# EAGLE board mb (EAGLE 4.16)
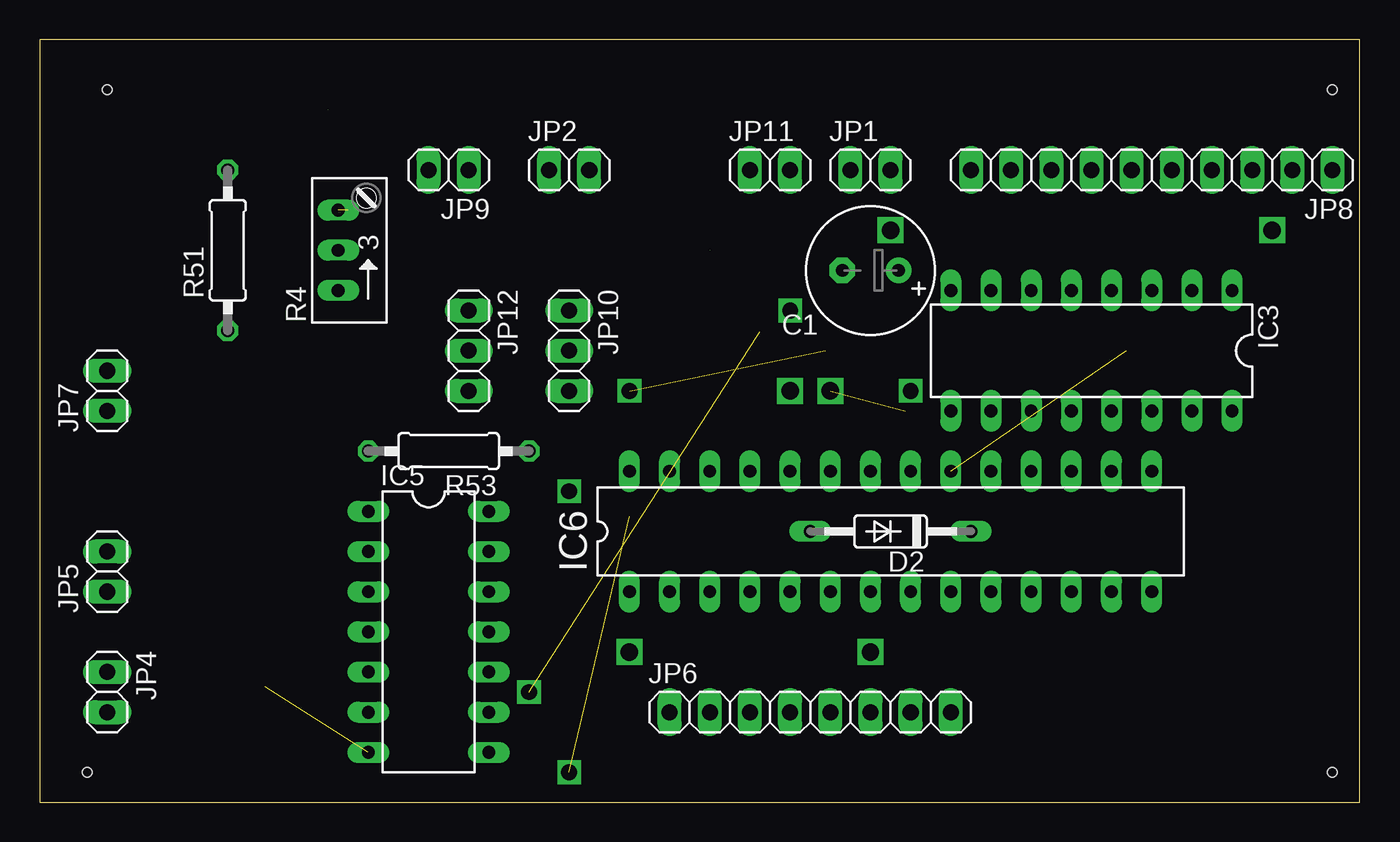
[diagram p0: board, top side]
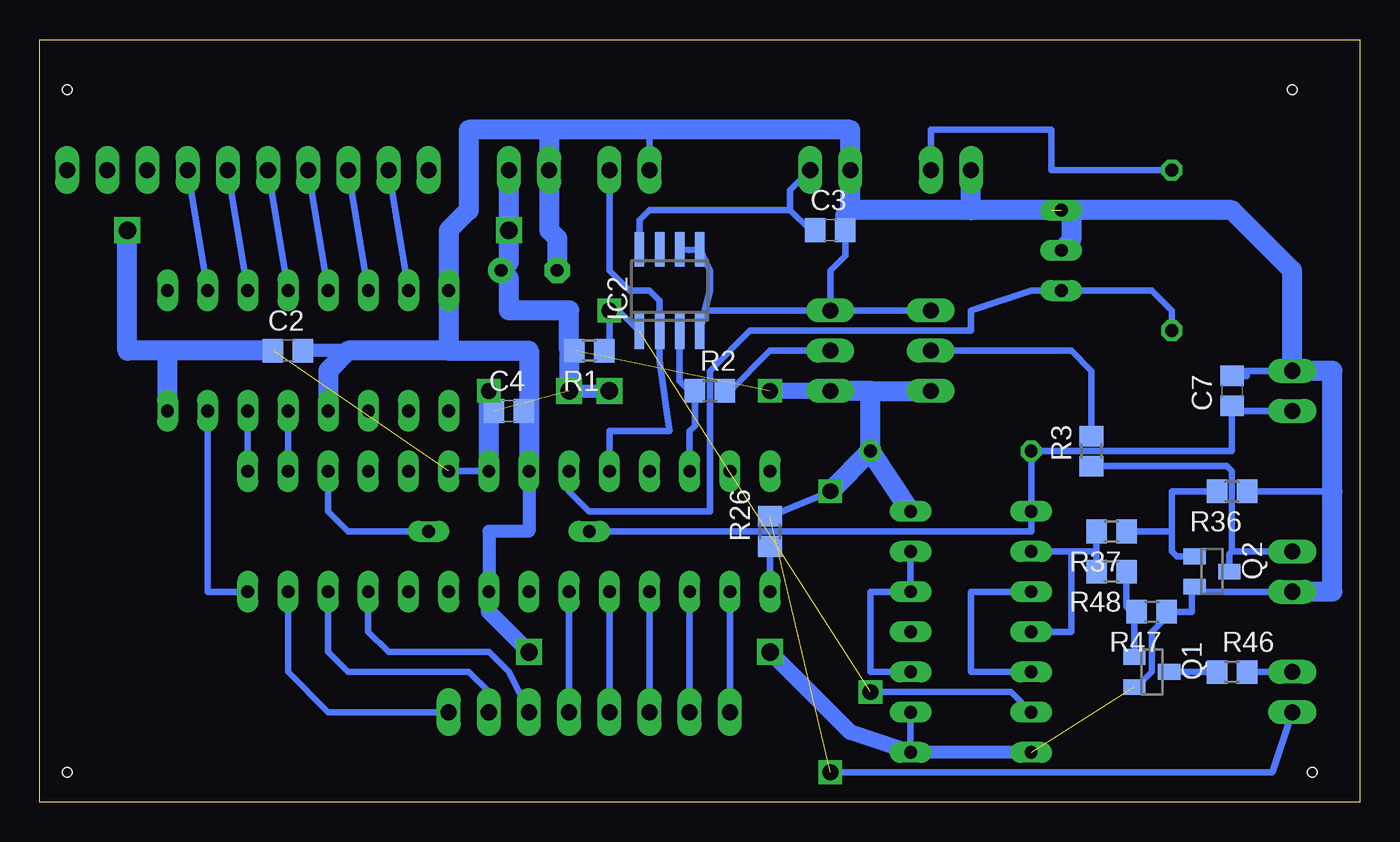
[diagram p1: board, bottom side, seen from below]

Size 83.49 x 48.25 mm. Coordinates in mm from the lower left corner, seen from the top.
Outline: 0,0 83.49,0 83.49,48.25 0,48.25 0,0
Copper layers (1*16): Top 0.035mm / dielectric 1.5mm / Bottom 0.035mm
Design rules "default": minimum track width 10mil, minimum drill 24mil, track to track 8mil, track to pad 8mil, pad to pad 8mil, via to via 8mil, smd to smd 8mil, copper to edge 40mil, drill to drill 8mil, minimum pad ring 10mil, minimum via ring 8mil, stop-mask expansion 4mil, vias tented up to drill 0mil, thermal gap 10mil
Holes 0.6 mm at 4.28,45.08 81.75,45.08 81.75,1.9 3.01,1.9

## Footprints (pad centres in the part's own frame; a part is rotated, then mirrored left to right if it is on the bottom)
E3,5-8 = drill 0.813 pad 1.6 round: + -1.778,0 | drill 0.813 pad 1.6 octagon: - 1.778,0
C0805 = smd 1.3 x 1.5: 1 -0.95,0; 2 0.95,0
DO35-10 = drill 0.813 long: A 5.08,0; C -5.08,0
SO08 = smd 0.6 x 2.2: 1 -1.905,-2.6; 2 -0.635,-2.6; 3 0.635,-2.6; 4 1.905,-2.6; 5 1.905,2.6; 6 0.635,2.6; 7 -0.635,2.6; 8 -1.905,2.6
DIL16 = drill 0.813 long: 1 -8.89,-3.81; 2 -6.35,-3.81; 3 -3.81,-3.81; 4 -1.27,-3.81; 5 1.27,-3.81; 6 3.81,-3.81; 7 6.35,-3.81; 8 8.89,-3.81; 9 8.89,3.81; 10 6.35,3.81; 11 3.81,3.81; 12 1.27,3.81; 13 -1.27,3.81; 14 -3.81,3.81; 15 -6.35,3.81; 16 -8.89,3.81
DIL14 = drill 0.813 long: 1 -7.62,-3.81; 2 -5.08,-3.81; 3 -2.54,-3.81; 4 0,-3.81; 5 2.54,-3.81; 6 5.08,-3.81; 7 7.62,-3.81; 8 7.62,3.81; 9 5.08,3.81; 10 2.54,3.81; 11 0,3.81; 12 -2.54,3.81; 13 -5.08,3.81; 14 -7.62,3.81
DIL28-3 = drill 0.813 long: 1 -16.51,-3.81; 2 -13.97,-3.81; 3 -11.43,-3.81; 4 -8.89,-3.81; 5 -6.35,-3.81; 6 -3.81,-3.81; 7 -1.27,-3.81; 8 1.27,-3.81; 9 3.81,-3.81; 10 6.35,-3.81; 11 8.89,-3.81; 12 11.43,-3.81; 13 13.97,-3.81; 14 16.51,-3.81; 15 16.51,3.81; 16 13.97,3.81; 17 11.43,3.81; 18 8.89,3.81; 19 6.35,3.81; 20 3.81,3.81; 21 1.27,3.81; 22 -1.27,3.81; 23 -3.81,3.81; 24 -6.35,3.81; 25 -8.89,3.81; 26 -11.43,3.81; 27 -13.97,3.81; 28 -16.51,3.81
1X02 = drill 1.016 long: 1 -1.27,0; 2 1.27,0
1X08 = drill 1.016 long: 1 -8.89,0; 2 -6.35,0; 3 -3.81,0; 4 -1.27,0; 5 1.27,0; 6 3.81,0; 7 6.35,0; 8 8.89,0
1X10 = drill 1.016 long: 1 -11.43,0; 2 -8.89,0; 3 -6.35,0; 4 -3.81,0; 5 -1.27,0; 6 1.27,0; 7 3.81,0; 8 6.35,0; 9 8.89,0; 10 11.43,0
1X03 = drill 1.016 long: 1 -2.54,0; 2 0,0; 3 2.54,0
SOT23 = smd 1 x 1.4: 1 -0.95,-1.1; 2 0.95,-1.1; 3 0,1.1
R0805 = smd 1.3 x 1.5: 1 -0.95,0; 2 0.95,0
RJ9W = drill 0.813 long: A 2.54,0.635; E -2.54,0.635; S 0,0.635
0207/10 = drill 0.813 octagon: 1 -5.08,0; 2 5.08,0

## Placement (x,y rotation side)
C1  10uF 10V  [E3,5-8]  52.54,33.65 180 top
C2  0.1uF  [C0805]  67.78,28.57 0 bottom
C3  [C0805]  33.49,36.19 0 bottom
C4  0.1uF  [C0805]  53.81,24.76 0 bottom
C7  [C0805]  8.09,26.03 90 bottom
D2  BA243A  [DO35-10]  53.81,17.14 180 top
IC2  LM393AN  [SO08]  43.65,32.38 0 bottom
IC3  74LS145N  [DIL16]  66.51,28.57 180 top
IC5  4011N  [DIL14]  24.6,10.79 270 top
IC6  MEGA8-P  [DIL28-3]  53.81,17.14 0 top
JP1  [1X02]  52.54,40 0 top
JP2  [1X02]  33.49,40 0 top
JP4  [1X02]  4.28,6.98 270 top
JP5  [1X02]  4.28,14.6 90 top
JP6  [1X08]  48.73,5.71 0 top
JP7  [1X02]  4.28,26.03 90 top
JP8  [1X10]  70.32,40 180 top
JP9  [1X02]  25.87,40 180 top
JP10  [1X03]  33.49,28.57 270 top
JP11  [1X02]  46.19,40 0 top
JP12  [1X03]  27.14,28.57 270 top
Q1  BC847BSMD  [SOT23]  13.17,8.25 270 bottom
Q2  BC847BSMD  [SOT23]  9.36,14.6 270 bottom
R1  4.7k  [R0805]  48.73,28.57 180 bottom
R2  100  [R0805]  41.11,26.03 0 bottom
R3  100  [R0805]  16.98,22.22 90 bottom
R4  3.3k  [RJ9W]  19.52,34.92 90 top
R26  4.7k  [R0805]  37.3,17.14 90 bottom
R36  10k  [R0805]  8.09,19.68 180 bottom
R37  2.2k  [R0805]  15.71,17.14 180 bottom
R46  [R0805]  8.09,8.25 0 bottom
R47  10k  [R0805]  13.17,12.06 180 bottom
R48  2.2k  [R0805]  15.71,14.6 180 bottom
R51  8.2k  [0207/10]  11.9,34.92 90 top
R53  4.7k  [0207/10]  25.87,22.22 180 top

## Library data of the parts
C1-C4 C7 R1-R3 R26 R36 R37 R46-R48 R51 R53 = rcl
D2 = diode
IC2 = linear
IC3 = 74xx-eu
IC5 = 40xx
IC6 = atmel
JP1 JP2 JP4-JP12 = pinhead
Q1 Q2 = transistor-npn
R4 = pot

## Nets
GND: C1.- C2.2 C3.2 C4.2 C7.2 IC2.4 IC2.5 IC2.6 IC3.8 IC3.12 IC5.7 IC5.8 IC5.9 IC6.8 IC6.22 JP1.1 JP2.1 JP5.1 JP7.2 JP9.2 JP10.1 JP11.1 JP12.1 Q1.2 Q2.2 R4.A R4.S R36.1 R47.1
N$1: IC6.2 JP6.1
N$2: IC6.3 JP6.2
N$3: IC6.4 JP6.3
N$4: IC6.5 JP6.4
N$5: IC2.2 IC6.24 JP11.2
N$6: IC3.15 IC6.14
N$7: IC6.1 R26.1
N$8: IC3.14 IC6.15
N$9: IC3.13 IC6.16
N$10: IC6.6 JP6.5
N$11: IC6.11 JP6.6
N$12: C7.1 D2.A IC5.1 JP7.1 R53.2
N$13: JP12.2 R3.2
N$14: IC6.12 JP6.7
N$15: JP10.2 R2.2
N$16: IC6.13 JP6.8
N$26: IC5.10 IC5.12 IC5.13
N$34: JP5.2 Q2.3 R3.1
N$35: Q2.1 R36.2 R37.1
N$36: IC5.2 IC5.4 R37.2 R48.2
N$37: IC3.16
N$39: C3.1 IC2.8 JP2.2
N$41: IC2.3 IC6.26 R2.1
N$44: IC3.2 JP8.4
N$45: IC3.3 JP8.5
N$46: IC3.4 JP8.6
N$47: IC3.5 JP8.7
N$48: IC3.6 JP8.8
N$49: IC3.7 JP8.9
N$66: Q1.3 R46.1
N$67: JP4.1 R46.2
N$68: Q1.1 R47.2 R48.1
N$74: JP9.1 R51.2
N$76: IC6.23 R4.E R51.1
N$81: IC2.1 IC5.6 R1.1
N$98: D2.C IC6.17
N$105: IC5.3 IC5.5
VCC: C1.+ C2.1 C4.1 IC5.14 IC6.20 IC6.21 JP1.2 JP4.2 JP10.3 JP12.3 R1.2 R26.2 R53.1

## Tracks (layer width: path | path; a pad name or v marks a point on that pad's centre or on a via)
GND  (via drill 1.1)  (2 unrouted)
  Bottom 0.406: JP5.1 10.63,13.33 | 32.54,37.14 C3.2 32.54,34.6 33.49,33.65 JP10.1 | 44.92,42.54 JP11.1 | 7.14,26.98 C7.2 8.09,27.3 JP7.2 | 11.9,12.06 10.63,12.06 10.63,13.33 | 10.63,13.33 10.46,13.5 Q2.2 | Q1.2 14.12,7.3 13.17,8.25 13.17,10.79 11.9,12.06 | 11.9,12.06 R47.1 | 41.4,31.18 IC2.4 | 41.4,31.18 41.11,32.38 41.11,33.65 IC2.5 42.38,34.92 IC2.6 | IC5.8 IC5.9 | 41.4,31.18 41.11,31.11 JP10.1 | JP10.1 JP12.1 | 1.74,19.68 R36.1
  Bottom 0.813: IC6.8 55.08,17.14 52.54,17.14 IC6.22 | IC5.7 IC5.8 | 63.97,28.57 C2.2
  Bottom 1.016: IC6.8 55.08,12.06 v52.54,9.52 | IC5.8 32.22,4.44 37.3,9.52
  Bottom 1.27: C1.- 50.76,35.68 51.27,36.19 JP1.1 51.27,42.54 | 51.27,42.54 56.35,42.54 56.35,37.46 57.62,36.19 IC3.8 57.62,28.57 | 51.27,42.54 44.92,42.54 32.22,42.54 JP2.1 32.22,37.46 | 57.62,28.57 52.54,28.57 52.54,24.76 | 52.54,24.76 C4.2 | 52.54,24.76 IC6.22 | IC3.12 65.24,27.3 63.97,28.57 57.62,28.57 | 32.22,37.46 32.54,37.14 | 24.6,37.46 JP9.2 | 24.6,37.46 32.22,37.46 | 24.6,37.46 19.52,37.46 18.25,37.46 | 18.25,37.46 8.09,37.46 4.28,33.65 JP7.2 1.74,27.3 1.74,19.68 1.74,13.33 JP5.1 | R4.S 18.25,35.55 18.25,37.46
N$1
  Bottom 0.406: IC6.2 JP6.1
N$2
  Bottom 0.406: IC6.3 JP6.2
N$3
  Bottom 0.406: IC6.4 JP6.3
N$4
  Bottom 0.406: IC6.5 JP6.4
N$5
  Bottom 0.406: IC6.24 47.46,23.49 43.65,23.49 44.28,27.93 IC2.2 44.28,31.75 44.92,32.38 46.19,32.38 47.46,33.65 JP11.2
N$6
  Bottom 0.406: IC6.14 72.86,13.33 IC3.15
N$7
  Bottom 0.406: R26.1 IC6.1
N$8
  Bottom 0.406: IC6.15 IC3.14
N$9
  Bottom 0.406: IC3.13 IC6.16
N$10
  Bottom 0.406: IC6.6 JP6.5
N$11
  Bottom 0.406: JP6.6 53.81,8.25 55.08,9.52 61.43,9.52 62.7,10.79 IC6.11
N$12
  Bottom 0.406: D2.A 20.79,17.14 IC5.1 R53.2 8.09,22.22 C7.1 8.09,24.76 JP7.1
N$13
  Bottom 0.406: R3.2 16.98,27.3 18.25,28.57 JP12.2
N$14
  Bottom 0.406: JP6.7 55.08,6.98 56.35,8.25 63.97,8.25 65.24,9.52 IC6.12
N$15
  Bottom 0.406: R2.2 39.84,26.03 37.3,28.57 JP10.2
N$16
  Bottom 0.406: JP6.8 65.24,5.71 67.78,8.25 IC6.13
N$17  (via drill 1)
  other vias: 37.3,26.03
N$18  (via drill 1.1)
  Bottom 0.813: v50,26.03 v47.46,26.03
N$19  (via drill 1)
  other vias: 47.46,31.11
N$20  (via drill 1)
  other vias: 30.95,6.98
N$21  (via drill 1.1)
  other vias: 77.94,36.19
N$24  (via drill 1)
  other vias: 33.49,19.68
N$25  (via drill 1)
  other vias: 33.49,1.9
N$26
  Bottom 0.406: IC5.10 30.95,8.25 30.95,13.33 IC5.12 IC5.13
N$27  (via drill 1.1)
  other vias: 37.3,9.52
N$34
  Bottom 0.406: Q2.3 8.26,15.7 8.09,15.87 | JP5.2 8.09,15.87 | R3.1 8.41,21.27 8.09,20.95 8.09,15.87
N$35
  Bottom 0.406: Q2.1 11.58,15.55 11.9,15.87 11.9,17.14 | 11.9,17.14 R37.1 | R36.2 11.9,19.68 11.9,17.14
N$36
  Bottom 0.406: 18.25,15.87 IC5.2 | 18.25,15.87 18.25,10.79 IC5.4 | R48.2 16.98,14.6 16.66,14.92 16.66,15.87 | 16.66,15.87 R37.2 | 16.66,15.87 18.25,15.87
N$37
  Bottom 1.27: IC3.16 75.4,28.57
N$39
  Bottom 0.406: IC2.8 45.56,36.82 44.92,37.46 36.03,37.46 | C3.1 34.76,36.19 36.03,37.46 | 36.03,37.46 36.03,38.73 JP2.2
N$41
  Bottom 0.406: IC6.26 42.38,23.49 42.06,23.81 R2.1 42.38,26.03 43.02,26.66 IC2.3
N$44
  Bottom 0.406: IC3.2 JP8.4
N$45
  Bottom 0.406: IC3.3 JP8.5
N$46
  Bottom 0.406: IC3.4 JP8.6
N$47
  Bottom 0.406: IC3.5 JP8.7
N$48
  Bottom 0.406: IC3.6 JP8.8
N$49
  Bottom 0.406: IC3.7 JP8.9
N$66
  Bottom 0.406: R46.1 Q1.3
N$67
  Bottom 0.406: JP4.1 R46.2
N$68
  Bottom 0.406: R48.1 14.76,12.38 14.44,12.06 | 14.44,12.06 R47.2 | Q1.1 14.27,11.89 14.44,12.06
N$74
  Bottom 0.406: R51.2 19.52,40 19.52,42.54 27.14,42.54 JP9.1
N$76
  Bottom 0.406: IC6.23 50,19.68 48.73,18.41 41.11,18.41 41.11,27.3 38.57,29.84 24.6,29.84 24.6,31.11 20.79,32.38 R4.E 13.17,32.38 11.9,31.11 R51.1
N$81  (1 unrouted)
  Bottom 0.406: IC2.1 46.89,31.11 47.46,31.11 47.46,28.57 R1.1 | IC5.6 22.06,6.98 30.95,6.98
N$93  (1 unrouted)
N$98
  Bottom 0.406: IC6.17 65.24,18.41 63.97,17.14 D2.C
N$100  (1 unrouted)
N$105
  Bottom 0.406: IC5.5 24.6,8.25 24.6,13.33 IC5.3
VCC  (via drill 1, 1.1)  (4 unrouted)
  Bottom 0.406: IC6.21 IC6.20 | JP4.2 5.55,1.9 33.49,1.9 | R26.2 33.49,19.68
  Bottom 1.016: JP10.3 37.3,26.03
  Bottom 1.27: 55.08,24.76 C4.1 | IC6.21 55.08,24.76 | 55.08,24.76 v55.08,26.03 | JP1.2 v53.81,36.19 53.81,34.16 C1.+ 53.81,33.14 53.81,31.11 50,31.11 50,28.57 R1.2 50,28.25 50,26.03 | C2.1 77.94,28.57 77.94,36.19 | 30.95,26.03 JP12.3 | 30.95,26.03 JP10.3 | R53.1 30.95,26.03 | IC5.14 R53.1 | R53.1 33.49,19.68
